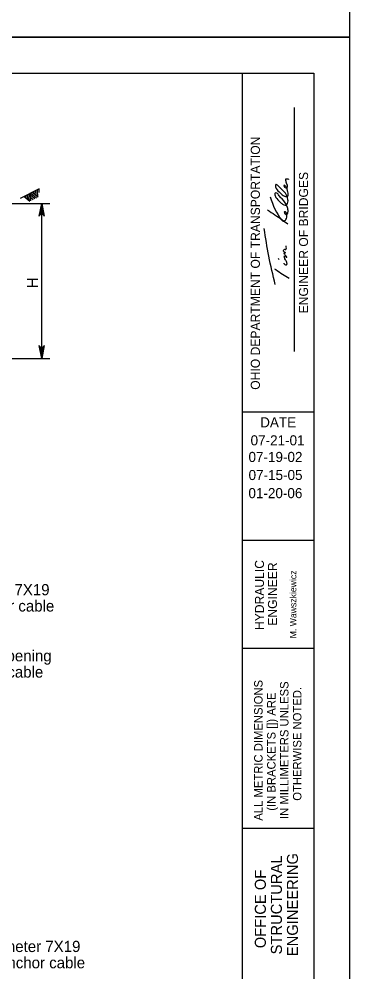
# Model space of a CAD drawing. Extents: x 1083.1 to 1117.1, y 675.4 to 741.4.
# Drawn here: x 1112.53 to 1117.13, y 706.36 to 719.6 of the extents above; entities that cross this region are included whole.
import ezdxf

# ---------------------------------------------------------------- set-up
doc = ezdxf.new("R2010")
doc.units = 0
doc.layers.add('Level 1', color=7, linetype='Continuous')

msp = doc.modelspace()

# ---------------------------------------------------------------- linework, layer by layer
at = {"layer": 'Level 1'}
for p, q in [((1115.636, 697.854), (1115.636, 718.854)), ((1116.355, 714.985), (1116.355, 718.375)), ((1112.551, 717.115), (1112.817, 717.248)), ((1112.629, 717.11), (1112.627, 717.151)), ((1112.652, 717.091), (1112.651, 717.163)), ((1112.673, 717.124), (1112.672, 717.173)), ((1112.697, 717.077), (1112.693, 717.184)), ((1112.774, 717.116), (1112.694, 717.181)), ((1112.751, 717.105), (1112.695, 717.15)), ((1112.796, 717.127), (1112.712, 717.194)), ((1112.744, 717.168), (1112.743, 717.209)), ((1112.769, 717.148), (1112.767, 717.221)), ((1112.793, 717.129), (1112.79, 717.232)), ((1112.81, 717.192), (1112.809, 717.242)), ((1111.929, 717.04), (1112.957, 717.04)), ((1112.68, 717.069), (1112.597, 717.136)), ((1112.675, 717.073), (1112.673, 717.124)), ((1112.728, 717.093), (1112.695, 717.12)), ((1112.822, 716.878), (1112.846, 717.04)), ((1112.832, 716.884), (1112.846, 717.04)), ((1112.846, 716.887), (1112.846, 717.04)), ((1112.858, 716.885), (1112.846, 717.04)), ((1112.869, 716.88), (1112.846, 717.04)), ((1112.846, 715.747), (1112.846, 717.04)), ((1116.145, 716.257), (1116.136, 716.276)), ((1112.846, 714.887), (1112.846, 715.747)), ((1112.824, 715.048), (1112.846, 714.887)), ((1112.835, 715.042), (1112.846, 714.887)), ((1112.871, 715.049), (1112.846, 714.887)), ((1112.861, 715.043), (1112.846, 714.887)), ((1112.846, 715.04), (1112.846, 714.887)), ((1111.929, 714.887), (1112.957, 714.887)), ((1116.626, 714.138), (1115.636, 714.138)), ((1116.626, 712.354), (1115.636, 712.354)), ((1116.626, 710.854), (1115.636, 710.854)), ((1116.626, 708.354), (1115.636, 708.354))]:
    msp.add_line(p, q, dxfattribs=at)
for points in [[(1083.126, 719.354), (1117.126, 719.354), (1117.126, 741.354), (1083.126, 741.354)], [(1083.126, 697.354), (1117.126, 697.354), (1117.126, 719.354), (1083.126, 719.354)], [(1083.126, 697.354), (1117.126, 697.354), (1117.126, 719.354), (1083.126, 719.354)], [(1085.126, 718.854), (1116.626, 718.854), (1116.626, 697.854), (1085.126, 697.854)]]:
    msp.add_lwpolyline(points, close=True, dxfattribs=at)
for points in [[(1112.811, 716.863), (1112.846, 717.04), (1112.882, 716.863)], [(1112.882, 715.064), (1112.846, 714.887), (1112.811, 715.064)]]:
    msp.add_lwpolyline(points, dxfattribs=at)
for centre, start, end in [((1112.846, 716.849), 22.0878, 157.9139), ((1112.846, 715.079), 202.0878, 337.9139)]:
    msp.add_arc(centre, 0.0382, start, end, dxfattribs=at)
for points in [[(1116.019, 717.132), (1116.184, 716.804), (1116.198, 716.793), (1116.207, 716.793), (1116.236, 716.817), (1116.249, 716.851), (1116.245, 716.902), (1116.23, 716.924), (1116.217, 716.924), (1116.216, 716.911), (1116.225, 716.896), (1116.237, 716.888), (1116.251, 716.888), (1116.264, 716.909), (1116.267, 716.929), (1116.258, 716.984), (1116.184, 717.104), (1116.143, 717.149), (1116.11, 717.184), (1116.087, 717.186), (1116.089, 717.147), (1116.112, 717.108), (1116.172, 717.046), (1116.21, 717.021), (1116.24, 717.016), (1116.261, 717.042), (1116.267, 717.076), (1116.263, 717.102), (1116.236, 717.175), (1116.209, 717.207), (1116.154, 717.261), (1116.128, 717.287), (1116.098, 717.302), (1116.095, 717.274), (1116.104, 717.248), (1116.156, 717.188), (1116.219, 717.141), (1116.266, 717.143), (1116.264, 717.201), (1116.254, 717.244), (1116.242, 717.269), (1116.233, 717.28), (1116.212, 717.295), (1116.213, 717.278), (1116.245, 717.257), (1116.258, 717.267), (1116.246, 717.321), (1116.239, 717.349), (1116.236, 717.362), (1116.236, 717.374), (1116.236, 717.383), (1116.258, 717.381), (1116.281, 717.381)], [(1115.984, 716.95), (1116.186, 716.813), (1116.263, 716.757)], [(1116.089, 715.913), (1116, 716.308), (1115.936, 716.691)], [(1116.207, 716.212), (1116.214, 716.201), (1116.248, 716.188), (1116.252, 716.221), (1116.23, 716.257), (1116.216, 716.293), (1116.216, 716.313), (1116.23, 716.306), (1116.239, 716.296), (1116.248, 716.291), (1116.227, 716.323), (1116.216, 716.338), (1116.213, 716.356), (1116.234, 716.349), (1116.227, 716.358), (1116.204, 716.386), (1116.213, 716.401), (1116.228, 716.403), (1116.236, 716.401), (1116.245, 716.422), (1116.239, 716.45)], [(1116.283, 715.997), (1116.098, 716.117), (1116.084, 716.128)]]:
    msp.add_spline(points, degree=3, dxfattribs=at)

# ---------------------------------------------------------------- texts
for s, height, rotation, p in [('OHIO DEPARTMENT OF TRANSPORTATION', 0.126, 90, (1115.876, 714.451)), ('ENGINEER OF BRIDGES', 0.126, 90, (1116.545, 715.513)), ('H', 0.156, 90, (1112.797, 715.863)), ('DATE', 0.14, 360, (1115.88, 713.928)), ('HYDRAULIC', 0.126, 90, (1115.933, 711.111)), ('ENGINEER', 0.126, 90, (1116.114, 711.171)), ('M. Wawszkiewicz', 0.09, 90, (1116.383, 710.996)), ('ALL METRIC DIMENSIONS', 0.117, 90, (1115.913, 708.461)), ('IN MILLIMETERS UNLESS', 0.117, 90, (1116.273, 708.484)), ('OTHERWISE NOTED.', 0.117, 90, (1116.453, 708.738)), ('(IN BRACKETS []) ARE', 0.117, 90, (1116.093, 708.599)), ('STRUCTURAL', 0.153, 90, (1116.182, 706.602)), ('ENGINEERING', 0.153, 90, (1116.405, 706.578)), ('OFFICE OF', 0.153, 90, (1115.959, 706.688))]:
    msp.add_text(s, height=height, rotation=rotation, dxfattribs=at).set_placement(p)
for s, height, p in [('07-21-01', 0.14, (1115.747, 713.678)), ('07-19-02', 0.14, (1115.718, 713.447)), ('07-15-05', 0.14, (1115.719, 713.196)), ('01-20-06', 0.14, (1115.717, 712.944)), ('3/8" [10] diameter 7X19', 0.156, (1110.771, 711.594)), ('galvanized anchor cable', 0.156, (1110.771, 711.368)), ('diameter opening', 0.156, (1111.372, 710.676)), ('for anchor cable', 0.156, (1111.372, 710.45)), ('3/8" [10] diameter 7X19', 0.156, (1111.199, 706.635)), ('galvanized anchor cable', 0.156, (1111.199, 706.409))]:
    msp.add_text(s, height=height, dxfattribs=at).set_placement(p)

doc.saveas('drawing.dxf')
